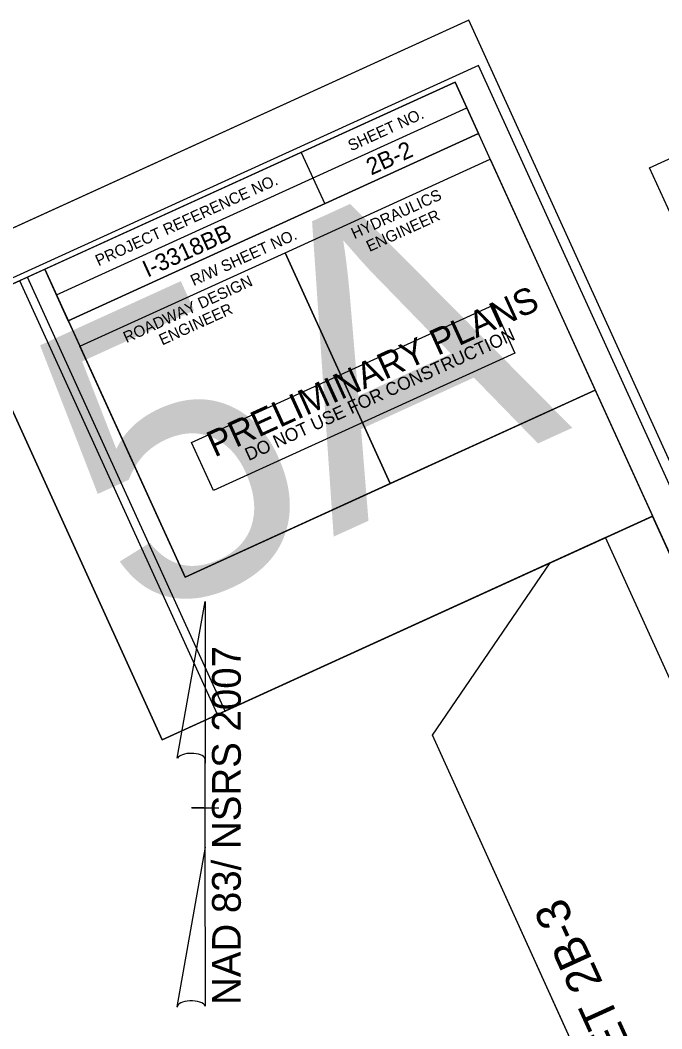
# Model space of a CAD drawing. Extents: x 2247910 to 2249896, y 662531 to 664300.
# Drawn here: x 2249242.3 to 2249527.1, y 663778.5 to 664225.8 of the extents above; entities that cross this region are included whole.
import ezdxf

# ---------------------------------------------------------------- set-up
doc = ezdxf.new("R2010")
doc.units = 0
for name, color, linetype in [('Matchline', 7, 'Continuous'), ('Matchline Text', 7, 'Continuous'), ('Prop North Arrow NAD83 for Plan Sheets CELL', 7, 'Continuous'), ('Sheet Clip Boundary CELL', 7, 'Continuous'), ('Sheet Cutting Line CELL', 7, 'Continuous'), ('Sheet Data Field CELL', 7, 'Continuous'), ('Sheet Layout Plan Border', 7, 'Continuous'), ('Sheet Plan CELL', 7, 'Continuous'), ('Sheet Plan Layout CELL', 7, 'Continuous'), ('Sheet Plot Border Inside CELL', 7, 'Continuous'), ('Sheet Plot Border Outside CELL', 7, 'Continuous'), ('Sheet Sticker Incomplete CELL', 7, 'Continuous'), ('Sheet Sticker Preliminary CELL', 7, 'Continuous')]:
    doc.layers.add(name, color=color, linetype=linetype)

msp = doc.modelspace()

# ---------------------------------------------------------------- linework, layer by layer
at = {"layer": 'Matchline'}
msp.add_line((2249673.42, 663362.44), (2249425.27, 663908.72), dxfattribs=at)
at = {"layer": 'Prop North Arrow NAD83 for Plan Sheets CELL'}
for p, q in [((2249312.07, 663898.49), (2249324.37, 663968.01)), ((2249324.45, 663968.01), (2249324.37, 663968.01)), ((2249324.45, 663968.01), (2249324.37, 663968.01)), ((2249324.45, 663968.01), (2249324.45, 663896.31)), ((2249324.45, 663859.11), (2249324.45, 663898.41)), ((2249324.45, 663896.31), (2249324.45, 663898.34)), ((2249318.45, 663876.51), (2249318.37, 663876.51)), ((2249323.77, 663876.51), (2249318.45, 663876.51)), ((2249318.52, 663876.51), (2249330.52, 663876.51)), ((2249324.45, 663859.11), (2249311.92, 663788.24)), ((2249324.52, 663788.54), (2249324.45, 663859.11))]:
    msp.add_line(p, q, dxfattribs=at)
for centre, start_param, end_param in [((2249318.28, 663897.74), 0.216388, 2.908219), ((2249318.28, 663787.99), 0.201328, 3.141593)]:
    msp.add_ellipse(centre, major_axis=(6.35, -0.05), ratio=0.461098, start_param=start_param, end_param=end_param, dxfattribs=at)
at = {"layer": 'Sheet Clip Boundary CELL'}
msp.add_lwpolyline([(2248112.28, 663594.05), (2248115.54, 663587.01), (2248212.22, 663373.68), (2248234.7, 663383.7), (2248241.67, 663371.06), (2248523.8, 662749.97), (2248551.22, 662641.58), (2249638.09, 663136.85), (2249825.2, 663222.11), (2249759.42, 663344.83), (2249697.59, 663317.15), (2249673.42, 663362.44), (2249425.27, 663908.72), (2249477.5, 663985.14), (2249333.25, 663919.41), (2249245.56, 664111.86), (2248806.18, 663911.31), (2248826.45, 663856.95), (2248820.45, 663848.41), (2248540.82, 663728.18), (2248517.28, 663777.91), (2248115.83, 663597.06)], close=True, dxfattribs=at)
at = {"layer": 'Sheet Cutting Line CELL'}
msp.add_line((2249441.45, 664225.83), (2247909.5, 663527.75), dxfattribs=at)
at = {"layer": 'Sheet Layout Plan Border'}
msp.add_lwpolyline([(2248198.13, 663481.51), (2248575.77, 662652.77), (2249849.75, 663233.3), (2249502.05, 663996.33), (2249329.83, 663917.85), (2249242.13, 664110.3), (2248140.38, 663608.25)], close=True, dxfattribs=at)
at = {"layer": 'Sheet Plan CELL'}
for p, q in [((2249258.45, 664103.96), (2249440.49, 664186.9)), ((2249263.66, 664092.55), (2249445.68, 664175.52)), ((2249263.66, 664092.55), (2249445.68, 664175.52)), ((2249367.05, 664167.15), (2249377.46, 664144.42)), ((2249359.88, 664122.68), (2249406.53, 664020.34)), ((2249263.66, 664092.55), (2249268.84, 664081.19))]:
    msp.add_line(p, q, dxfattribs=at)
for points in [[(2249435.32, 664198.33), (2248070.33, 663576.33), (2248505.72, 662620.85), (2249870.7, 663242.85)], [(2249253.26, 664115.38), (2249435.32, 664198.33), (2249445.68, 664175.52), (2249263.66, 664092.55)], [(2249359.88, 664122.68), (2249450.86, 664164.15), (2249497.53, 664061.77), (2249406.53, 664020.29)], [(2249268.84, 664081.19), (2249359.88, 664122.68), (2249406.53, 664020.29), (2249315.49, 663978.83)], [(2248505.72, 662620.85), (2248070.31, 663576.29), (2249253.26, 664115.38), (2249315.49, 663978.83), (2249497.53, 664061.77), (2249870.7, 663242.85)]]:
    msp.add_lwpolyline(points, close=True, dxfattribs=at)
at = {"layer": 'Sheet Plan Layout CELL'}
for points in [[(2249305.27, 663906.66), (2249523.01, 664005.88), (2249435.34, 664198.34), (2249217.58, 664099.11)], [(2248070.31, 663576.29), (2248505.72, 662620.85), (2249870.68, 663242.84), (2249522.99, 664005.87), (2249305.27, 663906.66), (2249217.58, 664099.11)]]:
    msp.add_lwpolyline(points, close=True, dxfattribs=at)
at = {"layer": 'Sheet Plot Border Inside CELL'}
msp.add_lwpolyline([(2248367.09, 662554.92), (2249883.1, 663245.75), (2249445.65, 664205.77), (2247929.62, 663514.94)], close=True, dxfattribs=at)
at = {"layer": 'Sheet Plot Border Outside CELL'}
msp.add_lwpolyline([(2248363.56, 662531.33), (2249895.5, 663229.41), (2249441.45, 664225.83), (2247909.5, 663527.75)], close=True, dxfattribs=at)
at = {"layer": 'Sheet Sticker Incomplete CELL'}
msp.add_lwpolyline([(2249531.33, 664138.99), (2249521.59, 664160.37), (2249655.35, 664221.33), (2249665.1, 664199.94)], close=True, dxfattribs=at)
at = {"layer": 'Sheet Sticker Preliminary CELL'}
msp.add_lwpolyline([(2249328.14, 664017.17), (2249318.39, 664038.56), (2249452.16, 664099.51), (2249461.91, 664078.13)], close=True, dxfattribs=at)

# ---------------------------------------------------------------- texts
at = {"layer": 'Matchline Text'}
msp.add_text('MATCHLINE -L- STA. 30+50.00 SEE SHEET 2B-3', height=15, rotation=114.4979, dxfattribs=at).set_placement((2249670.95, 663426.13))
at = {"layer": 'Prop North Arrow NAD83 for Plan Sheets CELL'}
msp.add_text('NAD 83/ NSRS 2007', height=12.75, rotation=90, dxfattribs=at).set_placement((2249340.23, 663789.06))
at = {"layer": 'Sheet Data Field CELL'}
for s, p in [('2B-2', (2249398.06, 664156.9)), ('I-3318BB', (2249298.8, 664111.6))]:
    msp.add_text(s, height=7.5, rotation=24.4979, dxfattribs=at).set_placement(p)
at = {"layer": 'Sheet Plan CELL'}
for s, height, p in [('SHEET NO.', 5, (2249389.2, 664167.62)), ('PROJECT REFERENCE NO.', 5.0001, (2249277.08, 664116.65)), ('HYDRAULICS', 5, (2249390.62, 664128.69)), ('ENGINEER', 5, (2249397.34, 664123)), ('R/W SHEET NO.', 5.0001, (2249319.34, 664107.83)), ('ROADWAY DESIGN', 5.0001, (2249289.49, 664082.58)), ('ENGINEER', 5, (2249305.35, 664081.52))]:
    msp.add_text(s, height=height, rotation=24.4979, dxfattribs=at).set_placement(p)
at = {"layer": 'Sheet Plan Layout CELL'}
msp.add_text('5A', height=131.25, rotation=24.4979, dxfattribs=at).set_placement((2249292.31, 663956.16))
at = {"layer": 'Sheet Sticker Preliminary CELL'}
for s, height, p in [('PRELIMINARY PLANS', 11.52, (2249328.6, 664031.83)), ('DO NOT USE FOR CONSTRUCTION', 5.76, (2249343.71, 664030.26))]:
    msp.add_text(s, height=height, rotation=24.4979, dxfattribs=at).set_placement(p)

doc.saveas('drawing.dxf')
